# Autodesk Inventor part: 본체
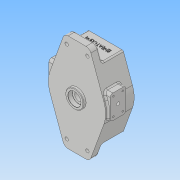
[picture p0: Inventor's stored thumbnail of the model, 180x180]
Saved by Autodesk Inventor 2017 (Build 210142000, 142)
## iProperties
Part Number: 본체
Material: 일반
Document SubType Name: Modeling
Designer: MRC
Density: 1 g/cm^3
Appearance: 기본값
Author: MRC
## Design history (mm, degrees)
sketch "스케치1"
  geometry: L1 (-51.683, 18.811)-(-33.78, 68); L2 (-24.317, 94)-(0, 94); L3 (0, 0)-(0, 94); L4 (0, 0)-(-58.53, 0); L5 (51.683, 18.811)-(33.78, 68); L6 (24.317, 94)-(0, 94); L7 (-51.683, -18.811)-(-33.78, -68); L8 (-24.317, -94)-(0, -94); L9 (51.683, -18.811)-(33.78, -68); L10 (24.317, -94)-(0, -94); L11 (-33.78, 68)-(33.78, 68); L12 (-33.78, -68)-(33.78, -68); L13 (-33.78, 68)-(-24.317, 94); L14 (33.78, 68)-(24.317, 94); L15 (33.78, -68)-(24.317, -94); L16 (-33.78, -68)-(-24.317, -94); A1 r 55 centre (0, 0) between (-51.683, 18.811) and (-51.683, -18.811); A2 r 55 centre (0, 0) between (51.683, -18.811) and (51.683, 18.811); 1 further point
  constraints: 32 end point, 8 tangent, 4 point on circle, 4 symmetric about line, 3 horizontal, 2 centre point, 1 coincident, 1 parallel, 1 vertical, 1 vertical alignment
  dimensions: "d3" = 20 deg angle of L3 L1; "d4" = 94 distance from line of point (0, 0) L2; "d6" = 136 distance between parallel lines of L12 L11; "d7" = 68 distance from line of L11 point (0, 0); "d8" = 55 radius of A2; "d9" = 55 radius of A1
extrude "돌출1" new body sketch "스케치1" distance "d10" = 15; taper "d11" = 0 deg
extrude "돌출2" join sketch "스케치1" distance "d12" = 55; taper "d13" = 0 deg
sketch "스케치3"
  geometry: C1 r 17.5 at (0, 0); A1 r 55 centre (0, 0) between (-51.683, 18.811) and (-51.683, -18.811) reference
  constraints: 1 centre point, 1 coincident
  dimensions: "d22" = 35 diameter of C1
extrude "돌출4" join sketch "스케치3" distance "d23" = 5; taper "d24" = 0 deg
sketch "스케치4"
  geometry: L1 (-68, 15)-(-68, 55) reference; L2 (-68, 55)-(68, 55) reference; L3 (68, 55)-(68, 15) reference; L4 (68, 15)-(94, 15) reference; L5 (94, 15)-(94, 0) reference; L6 (94, 0)-(17.5, 0) reference; L7 (17.5, 0)-(17.5, -5) reference; L8 (17.5, -5)-(-17.5, -5) reference; L9 (-17.5, -5)-(-17.5, 0) reference; L10 (-17.5, 0)-(-94, 0) reference; L11 (-94, 0)-(-94, 15) reference; L12 (-94, 15)-(-68, 15) reference; L13 (-9, 5)-(27, 5); L14 (32, 10)-(32, 30); L15 (27, 35)-(-9, 35); L16 (-14, 30)-(-14, 10); L17 (9, 5)-(9, 35); A1 r 5 centre (27, 30) between (32, 30) and (27, 35); A2 r 5 centre (-9, 30) between (-9, 35) and (-14, 30); A3 r 5 centre (-9, 10) between (-14, 10) and (-9, 5); A4 r 5 centre (27, 10) between (27, 5) and (32, 10); 4 further points
  constraints: 10 end point, 8 point on circle, 8 tangent, 6 point on line, 4 centre point, 3 equal radius, 2 midpoint, 2 parallel, 1 horizontal, 1 perpendicular
  dimensions: "d25" = 9 distance from line of point (0, 0) L17; "d26" = 30 distance of point (32, 5) point (32, 35); "d27" = 46 distance of point (32, 35) point (-14, 35); "d28" = 5 distance between parallel lines of L13 L6; "d29" = 5 radius of A1 (derived)
extrude "돌출5" join sketch "스케치4" stored distance "d30" = 118; taper "d31" = 0 deg
sketch "스케치5"
  geometry: A1 r 55 centre (0, 0) between (51.683, -18.811) and (51.683, 18.811) reference; 1 further point
  constraints: 1 vertical alignment
  dimensions: "d32" = 9 distance of A1.centre point (0, 9)
hole "구멍1" sketch "스케치5" at (0, 9) diameter "d33" = 80; stored, may be unused: countersink angle "d37" = 90 deg, drill point angle "d39" = 0 deg; dims "d34" = 6, "d35" = 4, "d36" = 2, "d38" = 30
node "작업 평면1"
sketch "스케치6"
  geometry: L1 (-40, 55)-(40, 55) reference; L2 (0, 55)-(0, 28.705); L3 (-33.78, 55)-(-51.683, 55) reference; L4 (-47.5, 55)-(-47.5, 53.1); L5 (-47, 52.6)-(-43.9, 52.6); L6 (-43.4, 53.1)-(-43.4, 55); L7 (-43.4, 55)-(-47.5, 55); A1 r 0.5 centre (-43.9, 53.1) between (-43.9, 52.6) and (-43.4, 53.1); A2 r 0.5 centre (-47, 53.1) between (-47.5, 53.1) and (-47, 52.6); 2 further points
  constraints: 10 end point, 4 point on circle, 4 point on line, 4 tangent, 3 perpendicular, 2 centre point, 2 vertical, 1 equal radius, 1 midpoint
  dimensions: "d41" = 95 diameter of L4 L2; "d42" = 4.1 distance between parallel lines of L4 L6; "d43" = 2.4 distance of point (-43.4, 52.6) L6.end; "d44" = 0.5 radius of A1
revolve "회전1" sketch "스케치6" stored, may be unused: angle "d45" = 90 deg
sketch "스케치7"
  geometry: L1 (17.5, 0)-(17.5, -5) reference; L2 (17.5, -5)-(-17.5, -5) reference; L3 (-17.5, -5)-(-17.5, 0) reference; L4 (-17.5, 0)-(-94, 0) reference; L5 (-94, 0)-(-94, 15) reference; L6 (-94, 15)-(-68, 15) reference; L7 (-68, 15)-(-68, 55) reference; L8 (-68, 55)-(-38.5, 55) reference; L9 (-38.5, 55)-(-38.5, 53.1) reference; L10 (-38, 52.6)-(-34.9, 52.6) reference; L11 (-34.4, 53.1)-(-34.4, 55) reference; L12 (-34.4, 55)-(-31, 55) reference; L13 (-31, 55)-(-31, 25) reference; L14 (-31, 25)-(49, 25) reference; L15 (49, 25)-(49, 55) reference; L16 (49, 55)-(52.4, 55) reference; L17 (52.4, 55)-(52.4, 53.1) reference; L18 (52.9, 52.6)-(56, 52.6) reference; L19 (56.5, 53.1)-(56.5, 55) reference; L20 (56.5, 55)-(68, 55) reference; L21 (68, 55)-(68, 15) reference; L22 (68, 15)-(94, 15) reference; L23 (94, 15)-(94, 0) reference; L24 (94, 0)-(17.5, 0) reference; L25 (49, 25)-(-31, 25) reference; L26 (0, 25)-(0, -5); L27 (0, 25)-(10, 25); L28 (10, 25)-(10, 15); L29 (10, 15)-(8, 15); L30 (8, 15)-(8, 3.4); L31 (-9, 5)-(18.811, 5) reference; L32 (8, 3.4)-(12.3, 3.4); L33 (12.5, 3.2)-(12.5, -5); L34 (0, -5)-(12.5, -5); L35 (-17.5, -5)-(17.5, -5) reference; L36 (10, 25)-(0, 25); A1 r 0.5 centre (-38, 53.1) between (-38.5, 53.1) and (-38, 52.6) reference; A2 r 0.5 centre (-34.9, 53.1) between (-34.9, 52.6) and (-34.4, 53.1) reference; A3 r 0.5 centre (52.9, 53.1) between (52.4, 53.1) and (52.9, 52.6) reference; A4 r 0.5 centre (56, 53.1) between (56, 52.6) and (56.5, 53.1) reference; A5 r 0.2 centre (12.3, 3.2) between (12.5, 3.2) and (12.3, 3.4); 2 further points
  constraints: 18 end point, 5 point on line, 4 perpendicular, 2 point on circle, 2 tangent, 2 vertical, 1 centre point, 1 collinear, 1 midpoint, 1 parallel
  dimensions: "d46" = 20 diameter of L28 L26; "d47" = 16 diameter of L30 L26; "d48" = 25 diameter of L33 L26; "d49" = 10 distance of L27.end L28.end; "d50" = 8.4 distance of point (12.5, 3.4) L33.end; "d51" = 0.2 radius of A5
revolve "회전2" sketch "스케치7" stored, may be unused: angle "d52" = 90 deg
chamfer "모따기1" distance "d53" = 0.4; stored, may be unused: second distance "d54" = 2, angle "d55" = 30 deg
sketch "스케치8"
  geometry: L1 (-26.702, 6)-(-22.517, 6); L2 (-26.702, -6)-(-25.515, -6); L3 (-23.812, -6)-(23.812, -6); L4 (-18.735, 6)-(18.735, 6); L5 (22.517, 6)-(26.702, 6); L6 (25.515, -6)-(26.702, -6); C1 r 40 at (0, 0) reference; C2 r 8 at (0, -9) reference; A1 r 29 centre (0, 0) between (-28.373, -6) and (28.373, -6); A2 r 24 centre (0, -9) between (-20.785, 3) and (-23.552, -4.385); A3 r 29 centre (0, 0) between (-28.68, 4.296) and (-28.68, -4.296); A4 r 24 centre (0, -9) between (18.735, 6) and (-18.735, 6); A5 r 29 centre (0, 0) between (28.373, 6) and (-28.373, 6); A6 r 29 centre (0, 0) between (28.68, -4.296) and (28.68, 4.296); A7 r 24 centre (0, -9) between (23.552, -4.385) and (20.785, 3); A8 r 24 centre (0, -9) between (-23.812, -6) and (23.812, -6); A9 r 2 centre (-22.517, 4) between (-20.785, 3) and (-22.517, 6); A10 r 2 centre (-26.702, 4) between (-26.702, 6) and (-28.68, 4.296); A11 r 2 centre (-26.702, -4) between (-28.68, -4.296) and (-26.702, -6); A12 r 2 centre (-25.515, -4) between (-25.515, -6) and (-23.552, -4.385); A13 r 2 centre (25.515, -4) between (23.552, -4.385) and (25.515, -6); A14 r 2 centre (26.702, -4) between (26.702, -6) and (28.68, -4.296); A15 r 2 centre (26.702, 4) between (28.68, 4.296) and (26.702, 6); A16 r 2 centre (22.517, 4) between (22.517, 6) and (20.785, 3)
  constraints: 42 point on circle, 16 centre point, 16 tangent, 12 end point, 8 point on line, 7 equal radius, 6 horizontal, 2 coincident
  dimensions: "d56" = 58 diameter of A1; "d57" = 48 diameter of A2; "d58" = 6 distance from line of L2 C1.centre; "d59" = 6 distance from line of C1.centre L1; "d60" = 2 radius of A9
extrude "돌출6" cut sketch "스케치8" distance "d61" = 12; taper "d62" = 0 deg
sketch "스케치9"
  geometry: L1 (-5, -9)-(-5, 27) reference; L2 (-29, -8)-(-11, -8); L3 (-11, -8)-(-11, 26); L4 (-11, 26)-(-29, 26); L5 (-29, 26)-(-29, -8); L6 (-29, -8)-(-11, 26); L7 (-11, -8)-(-29, 26); 7 further points
  constraints: 12 end point, 5 coincident, 2 midpoint, 2 parallel, 1 horizontal, 1 perpendicular
  dimensions: "d63" = 9 vertical distance of point (0, 0) point (-20, 9); "d64" = 15 distance from line of L1 point (-20, 9); "d65" = 18 distance of L3.end L4.end; "d66" = 34 distance of L2.end L3.end
hole "구멍2" sketch "스케치9" diameter "d67" = 3.242; stored, may be unused: countersink angle "d71" = 90 deg, drill point angle "d73" = 118 deg; dims "d68" = 8, "d69" = 4, "d70" = 2, "d72" = 10
hole "구멍3" sketch "스케치9" diameter "d74" = 6; stored, may be unused: countersink angle "d78" = 90 deg, drill point angle "d80" = 118 deg; dims "d75" = 8, "d76" = 4, "d77" = 2, "d79" = 10
sketch "스케치10"
  geometry: A1 r 29 centre (0, 0) between (-28.68, 4.296) and (-28.68, -4.296) reference; 2 further points
  constraints: 1 horizontal alignment
  dimensions: "d81" = 30 distance of point (15, 17) point (-15, 17); "d82" = 17 vertical distance of A1.centre point (15, 17); "d83" = 15 horizontal distance of A1.centre point (-15, 17)
hole "구멍4" sketch "스케치10" at (-15, 17), (15, 17) diameter "d84" = 3.242; stored, may be unused: countersink angle "d88" = 90 deg, drill point angle "d90" = 118 deg; dims "d85" = 8, "d86" = 4, "d87" = 2, "d89" = 11.8
sketch "스케치11"
  geometry: L1 (-22.517, 15)-(-26.702, 15) reference; L2 (-26.702, 3)-(-25.515, 3) reference; L3 (25.515, 3)-(26.702, 3) reference; L4 (26.702, 15)-(22.517, 15) reference; L5 (33.78, -68)-(-33.78, -68) reference; L6 (-24.317, -94)-(-33.78, -68) reference; L7 (24.317, -94)-(-24.317, -94) reference; L8 (33.78, -68)-(24.317, -94) reference; L9 (51.683, -18.811)-(33.78, -68) reference; L10 (59, -14)-(53.188, -14) reference; L11 (59, 32)-(59, -14) reference; L12 (46.883, 32)-(59, 32) reference; L13 (33.78, 68)-(46.883, 32) reference; L14 (-33.78, 68)-(33.78, 68) reference; L15 (-33.78, 68)-(-24.317, 94) reference; L16 (-24.317, 94)-(24.317, 94) reference; L17 (24.317, 94)-(33.78, 68) reference; L18 (-33.78, -68)-(-51.683, -18.811) reference; L19 (-53.188, -14)-(-59, -14) reference; L20 (-59, -14)-(-59, 32) reference; L21 (-59, 32)-(-46.883, 32) reference; L22 (-46.883, 32)-(-33.78, 68) reference; L23 (-20, -79)-(20, -79); L24 (20, -79)-(20, 79); L25 (20, 79)-(-20, 79); L26 (-20, 79)-(-20, -79); L27 (-20, -79)-(20, 79); L28 (20, -79)-(-20, 79); C1 r 10 at (0, 0) reference; C2 r 8 at (0, 0) reference; C3 r 1.621 at (-15, 26) reference; C4 r 1.621 at (15, 26) reference; A1 r 2 centre (-26.702, 13) between (-26.702, 15) and (-28.68, 13.296) reference; A2 r 29 centre (0, 9) between (-28.68, 13.296) and (-28.68, 4.704) reference; A3 r 2 centre (-26.702, 5) between (-28.68, 4.704) and (-26.702, 3) reference; A4 r 2 centre (-25.515, 5) between (-25.515, 3) and (-23.552, 4.615) reference; A5 r 24 centre (0, 0) between (-20.785, 12) and (-23.552, 4.615) reference; A6 r 2 centre (-22.517, 13) between (-20.785, 12) and (-22.517, 15) reference; A7 r 2 centre (26.702, 5) between (26.702, 3) and (28.68, 4.704) reference; A8 r 29 centre (0, 9) between (28.68, 4.704) and (28.68, 13.296) reference; A9 r 2 centre (26.702, 13) between (28.68, 13.296) and (26.702, 15) reference; A10 r 2 centre (22.517, 13) between (22.517, 15) and (20.785, 12) reference; A11 r 24 centre (0, 0) between (23.552, 4.615) and (20.785, 12) reference; A12 r 2 centre (25.515, 5) between (23.552, 4.615) and (25.515, 3) reference; A13 r 55 centre (0, 0) between (51.683, -18.811) and (53.188, -14) reference; A14 r 55 centre (0, 0) between (-53.188, -14) and (-51.683, -18.811) reference; 5 further points
  constraints: 12 end point, 4 coincident, 2 midpoint, 2 parallel, 1 horizontal, 1 perpendicular
  dimensions: "d91" = 40 distance of L25.end L24.end; "d92" = 158 distance of L24.end L23.end
hole "구멍5" sketch "스케치11" at (-20, 79), (20, 79), (20, -79), (-20, -79) diameter "d93" = 6.6; stored, may be unused: countersink angle "d97" = 90 deg, drill point angle "d99" = 118 deg; dims "d94" = 8, "d95" = 11, "d96" = 6.6, "d98" = 10
sketch "스케치12"
  geometry: L1 (-25, -61)-(25, -61); L2 (25, -61)-(25, 61); L3 (25, 61)-(-25, 61); L4 (-25, 61)-(-25, -61); L5 (-25, -61)-(25, 61); L6 (25, -61)-(-25, 61); A1 r 55 centre (0, 0) between (-51.683, 18.811) and (-51.683, -18.811) reference; 4 further points
  constraints: 12 end point, 4 coincident, 2 midpoint, 2 parallel, 1 horizontal, 1 perpendicular
  dimensions: "d100" = 50 distance of L3.end L2.end; "d101" = 122 distance of L2.end L1.end
hole "구멍6" sketch "스케치12" at (-25, 61), (25, 61), (25, -61), (-25, -61) diameter "d102" = 4.917; stored, may be unused: countersink angle "d106" = 90 deg, drill point angle "d108" = 118 deg; dims "d103" = 12, "d104" = 11, "d105" = 6.6, "d107" = 14
sketch "스케치13"
  geometry: L1 (67.56, -40)-(0, -40) reference; L2 (8.892, -21.398)-(58.667, -21.398); L3 (58.667, -21.398)-(58.667, -28.602); L4 (58.667, -28.602)-(8.892, -28.602); L5 (8.892, -28.602)-(8.892, -21.398); L6 (8.892, -25)-(58.667, -25); L7 (33.78, -21.398)-(33.78, -28.602); 1 further point
  constraints: 4 end point, 4 midpoint, 1 vertical alignment, 2 other
  dimensions: "d109" = 15 distance from line of L1 L6.start
feature "엠보싱1" sketch "스케치13" dims "d3" = 20 deg, "d4" = 94, "d6" = 136, "d7" = 68, "d8" = 55, "d9" = 55, "d110" = 0.5, "d111" = 0
fillet "모깎기1" dims "d112" = 2
fillet "모깎기2" dims "d113" = 10
fillet "모깎기3" dims "d114" = 3
fillet "모깎기4" dims "d115" = 3
chamfer "모따기2" distance "d116" = 1; stored, may be unused: second distance "d117" = 2, angle "d118" = 30 deg
node "솔리드1"
mirror "미러1"
mirror "미러2"
node "절단 모서리 투영2"
node "절단 모서리 투영3"
node "절단 모서리 투영4"
other parameters: "d40" = 9
